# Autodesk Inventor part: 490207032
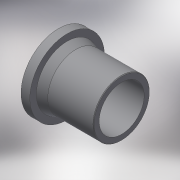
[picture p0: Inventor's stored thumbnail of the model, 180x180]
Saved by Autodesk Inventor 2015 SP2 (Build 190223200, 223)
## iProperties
Created: 2017-07
Part Number: 490207032
Material: Generic
Description: Stub Flange 32
Document SubType Name: Modeling
Designer: Кирилл
Mass: 56.0859 g
Surface Area: 227.117 cm^2
Volume: 56.0859 cm^3
Density: 1 g/cm^3
Appearance: Default
Author: Кирилл
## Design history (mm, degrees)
derived "490207.ipt"
feature "Solid1::490207.ipt"
tag "TaggingFeature1"
body "Solid1"
other parameters: "d0" = 85, "d2" = 32, "d3" = 25.6, "d4" = 68, "d16" = 32, "d17" = 0.64, "d18" = 0.64, "d19" = 0.64, "d21" = 0.64, "d24" = 0.64, "d25" = 0.64, "d26" = 0.32, "d27" = 0, "d32" = 0.32, "d_" = 32, "L_" = 85, "D_" = 68
